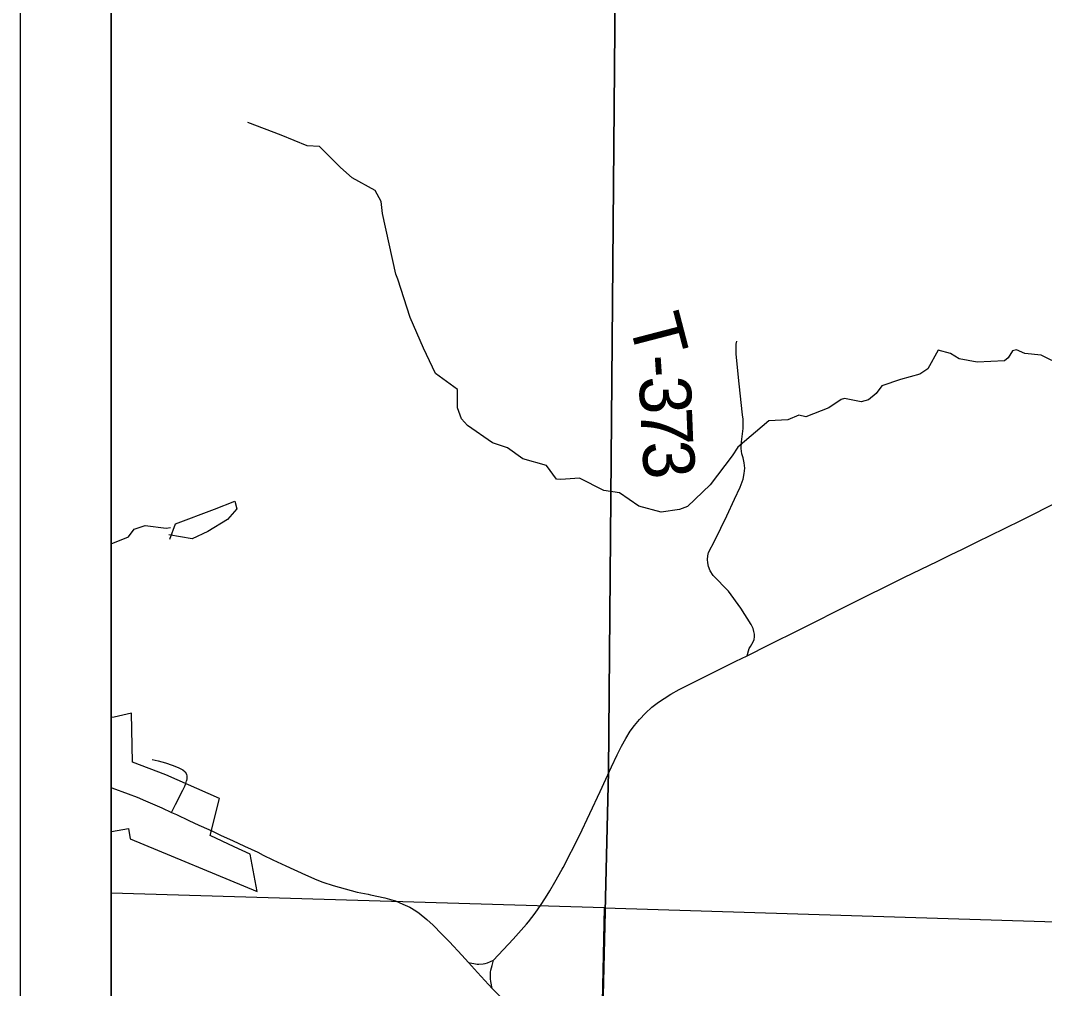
# Model space of a CAD drawing. Extents: x 0 to 34, y 0 to 22.
# Drawn here: x 2.5 to 3.628, y 15.568 to 16.635 of the extents above; entities that cross this region are included whole.
import ezdxf

# ---------------------------------------------------------------- set-up
doc = ezdxf.new("R2010")
doc.units = 0
for name, color, linetype in [('GM_X_City_Street', 7, 'Continuous'), ('GM_X_Corporation', 7, 'Continuous'), ('GM_X_Interchange_Ramps', 7, 'Continuous'), ('GM_X_Minor_River', 7, 'Continuous'), ('GM_X_State_Route', 7, 'Continuous'), ('GM_X_Township_Road', 7, 'Continuous'), ('GM_X_Township_Road_Text', 7, 'Continuous'), ('SH_Data', 7, 'Continuous')]:
    doc.layers.add(name, color=color, linetype=linetype)

msp = doc.modelspace()

# ---------------------------------------------------------------- linework, layer by layer
at = {"layer": 'GM_X_City_Street'}
msp.add_lwpolyline([(2.6666, 15.7621), (2.671, 15.7708), (2.6789, 15.7865), (2.6811, 15.7909), (2.6823, 15.7939), (2.6829, 15.7968)], dxfattribs=at)
at = {"layer": 'GM_X_Corporation'}
for points in [[(2.6, 16.6918), (2.6, 13.6), (9.4, 13.6), (9.4, 16.4853), (9.09, 16.4927), (8.0963, 16.5226), (6.2194, 16.578), (6.0834, 16.5816), (5.4202, 16.5982), (4.6351, 16.6229), (4.5473, 16.6256), (4.1867, 16.6352), (4.1011, 16.6362), (4.0515, 16.6368), (3.1684, 16.6682), (3.1555, 16.6686)], [(2.6, 16.6918), (2.6, 13.6417), (3.0575, 13.6324), (3.1025, 13.6315), (3.1033, 13.7653), (3.1089, 14.0542), (3.109, 14.0614), (3.1121, 14.2169), (3.1127, 14.2486), (3.1134, 14.2853), (3.1142, 14.3277), (3.1263, 14.9513), (3.1401, 15.483), (3.148, 15.8071), (3.1555, 16.6686)], [(2.6, 15.8668), (2.6, 15.7412), (2.6002, 15.7411), (2.6189, 15.7445), (2.6209, 15.733), (2.7607, 15.6749), (2.753, 15.716), (2.7355, 15.7241), (2.7092, 15.7367), (2.7193, 15.7774), (2.6602, 15.8034), (2.6234, 15.8176), (2.6224, 15.8716), (2.6031, 15.867)], [(2.6, 15.673), (2.6, 14.6526), (3.1218, 14.6372), (3.1435, 15.6571)], [(4.1616, 15.6255), (4.1372, 14.6117), (3.1218, 14.6372), (3.1435, 15.6571)]]:
    msp.add_lwpolyline(points, close=True, dxfattribs=at)
msp.add_lwpolyline([(3.1555, 16.6686), (3.148, 15.8071), (3.1401, 15.483), (3.1263, 14.9513), (3.1142, 14.3277), (3.1134, 14.2853), (3.1127, 14.2486), (3.1121, 14.2169), (3.109, 14.0614), (3.1089, 14.0542), (3.1033, 13.7653), (3.1025, 13.6315), (3.2812, 13.6297), (3.3525, 13.6282), (4.3222, 13.6092), (4.5781, 13.6), (9.4, 13.6)], dxfattribs=at)
at = {"layer": 'GM_X_Interchange_Ramps'}
msp.add_lwpolyline([(3.0198, 15.5683), (3.0182, 15.5759), (3.0179, 15.5787), (3.0178, 15.5816), (3.0179, 15.5836), (3.0181, 15.5863), (3.0184, 15.5885), (3.0196, 15.5936), (3.0212, 15.5994)], dxfattribs=at)
at = {"layer": 'GM_X_Minor_River'}
for points in [[(3.6488, 16.254), (3.6247, 16.2658), (3.6069, 16.2678), (3.5977, 16.2718), (3.5932, 16.2706), (3.5884, 16.263), (3.5842, 16.2595), (3.5543, 16.2583), (3.5345, 16.2618), (3.5249, 16.2677), (3.5112, 16.2713), (3.4997, 16.2507), (3.4911, 16.2449), (3.4699, 16.2392), (3.4492, 16.2321), (3.4428, 16.2237), (3.4346, 16.2167), (3.4263, 16.2143), (3.408, 16.2182), (3.4042, 16.217), (3.3907, 16.2077), (3.3654, 16.1979), (3.3578, 16.1997), (3.3457, 16.1946), (3.3245, 16.1935), (3.2904, 16.1646), (3.2841, 16.155), (3.2599, 16.1232), (3.2352, 16.0993), (3.2261, 16.0958), (3.2061, 16.0928), (3.1813, 16.0997), (3.1602, 16.1141), (3.1427, 16.1169), (3.116, 16.1305), (3.0955, 16.129), (3.0906, 16.1294), (3.0797, 16.1443), (3.0534, 16.1515), (3.0365, 16.1638), (3.0201, 16.1692), (2.9925, 16.1885), (2.986, 16.1959), (2.9816, 16.208), (2.9817, 16.2281), (2.9575, 16.2455), (2.9442, 16.2737), (2.9293, 16.3072), (2.9158, 16.3497), (2.9138, 16.355), (2.8988, 16.4218), (2.8974, 16.435), (2.8908, 16.4474), (2.8656, 16.4614), (2.8525, 16.4725), (2.8294, 16.4956), (2.8161, 16.4966), (2.7871, 16.5082), (2.7504, 16.522)], [(2.6646, 16.063), (2.6708, 16.0801), (2.7139, 16.0963), (2.7361, 16.105), (2.7385, 16.0967), (2.7281, 16.0848), (2.7066, 16.0716), (2.6893, 16.0634), (2.6634, 16.0679)], [(2.6, 16.0582), (2.6191, 16.0657), (2.6254, 16.0741), (2.6375, 16.0781), (2.6607, 16.0754), (2.6652, 16.0759)]]:
    msp.add_lwpolyline(points, dxfattribs=at)
at = {"layer": 'GM_X_State_Route'}
msp.add_line((2.7212, 15.7367), (2.7335, 15.7312), dxfattribs=at)
for points in [[(3.1513, 15.8125), (3.1575, 15.8254), (3.1623, 15.835), (3.1671, 15.8437), (3.1719, 15.8515), (3.1766, 15.858), (3.1821, 15.8646), (3.1886, 15.8715), (3.1957, 15.878), (3.203, 15.8835), (3.2092, 15.8878), (3.2167, 15.8925), (3.226, 15.8975), (3.2392, 15.9043), (3.2698, 15.9197), (3.2883, 15.9288), (3.3007, 15.9348), (3.3248, 15.9467), (3.359, 15.9638), (3.3744, 15.9715), (3.383, 15.9757), (3.3916, 15.9801), (3.3975, 15.9831), (3.4327, 16.0007), (3.453, 16.0108), (3.4743, 16.0213), (3.51, 16.0385), (3.5257, 16.0461), (3.5373, 16.0519), (3.5402, 16.0534), (3.5542, 16.0601), (3.5844, 16.075), (3.6038, 16.0846), (3.6438, 16.1047)], [(2.9938, 15.5969), (3.0033, 15.5951), (3.005, 15.595), (3.0099, 15.5953), (3.0121, 15.5957), (3.0147, 15.5966), (3.0212, 15.5994), (3.0429, 15.6224), (3.0578, 15.6391), (3.0597, 15.6415), (3.0673, 15.651), (3.0739, 15.6607), (3.078, 15.6671), (3.0822, 15.6738), (3.0834, 15.6758), (3.089, 15.6853), (3.0971, 15.6997), (3.0981, 15.7015), (3.116, 15.7367), (3.1387, 15.785), (3.1513, 15.8125)], [(2.6, 15.7895), (2.6006, 15.7893), (2.6187, 15.7826), (2.6285, 15.7788), (2.6377, 15.775), (2.6429, 15.7728), (2.6557, 15.7673), (2.6666, 15.7621)], [(2.6666, 15.7621), (2.6718, 15.7597), (2.6856, 15.7533), (2.6965, 15.748), (2.7074, 15.7433), (2.7115, 15.7413), (2.7212, 15.7367)], [(2.7335, 15.7312), (2.747, 15.7248), (2.7615, 15.7182), (2.7676, 15.7152)], [(2.7676, 15.7152), (2.7782, 15.7099), (2.7923, 15.7032), (2.814, 15.6933), (2.8264, 15.688), (2.833, 15.6854), (2.8445, 15.6816), (2.871, 15.6743), (2.8831, 15.6719), (2.8857, 15.6714), (2.9016, 15.668), (2.9119, 15.665), (2.9131, 15.6646), (2.9213, 15.6612), (2.929, 15.6577), (2.9308, 15.6567), (2.9367, 15.653), (2.9395, 15.6512), (2.9479, 15.6443), (2.9547, 15.638), (2.9643, 15.6281), (2.9726, 15.6194), (2.9865, 15.6049), (2.9938, 15.5969)], [(2.9938, 15.5969), (3.0002, 15.5896), (3.0036, 15.5859)], [(3.0036, 15.5859), (3.0198, 15.5683), (3.026, 15.5619), (3.0353, 15.5522), (3.0534, 15.5332), (3.0666, 15.5215), (3.0745, 15.5149), (3.0767, 15.5133), (3.085, 15.508), (3.0869, 15.5068), (3.0996, 15.4998), (3.1012, 15.4989), (3.114, 15.4933), (3.1293, 15.487), (3.1425, 15.4814)]]:
    msp.add_lwpolyline(points, dxfattribs=at)
at = {"layer": 'GM_X_Township_Road'}
for points in [[(3.3007, 15.9348), (3.3023, 15.9403), (3.303, 15.9429), (3.3043, 15.9451), (3.3075, 15.9502), (3.3085, 15.9528), (3.309, 15.9556), (3.3089, 15.9584), (3.3082, 15.9616), (3.3073, 15.9648), (3.3053, 15.9692), (3.2937, 15.987), (3.2801, 16.006), (3.2634, 16.0233), (3.2601, 16.0284), (3.2581, 16.033), (3.2574, 16.0371), (3.2572, 16.0408), (3.2575, 16.0448), (3.2583, 16.0484), (3.2652, 16.0618), (3.2783, 16.0889), (3.2868, 16.1071), (3.293, 16.1203), (3.2963, 16.1294), (3.2976, 16.1356), (3.2983, 16.1415), (3.2976, 16.1472), (3.2962, 16.1526), (3.2948, 16.1571), (3.2942, 16.163), (3.2945, 16.1704), (3.2962, 16.185), (3.2964, 16.1903), (3.2963, 16.1952), (3.2957, 16.2), (3.2919, 16.2344), (3.2887, 16.2669), (3.2885, 16.2728), (3.2888, 16.2779), (3.2895, 16.2813)], [(2.6452, 15.8204), (2.6518, 15.8188), (2.6597, 15.8166), (2.6672, 15.8142), (2.6737, 15.8116), (2.679, 15.8091), (2.6815, 15.807), (2.6828, 15.8044), (2.6832, 15.8019), (2.6833, 15.7994), (2.6829, 15.7968)]]:
    msp.add_lwpolyline(points, dxfattribs=at)
at = {"layer": 'SH_Data'}
for points in [[(2.5, 20.5), (9.5, 20.5), (9.5, 13.5), (2.5, 13.5)], [(2.6, 20.4), (9.4, 20.4), (9.4, 13.6), (2.6, 13.6)]]:
    msp.add_lwpolyline(points, close=True, dxfattribs=at)

# ---------------------------------------------------------------- texts
at = {"layer": 'GM_X_Township_Road_Text'}
for s, rotation, p in [('T', 284.609, (3.1699, 16.3033)), ('-', 273.8826, (3.1802, 16.265)), ('3', 272.207, (3.1817, 16.2421)), ('7', 272.2385, (3.1831, 16.2071)), ('3', 274.3873, (3.1846, 16.1698))]:
    msp.add_text(s, height=0.0568, rotation=rotation, dxfattribs=at).set_placement(p)

doc.saveas('drawing.dxf')
